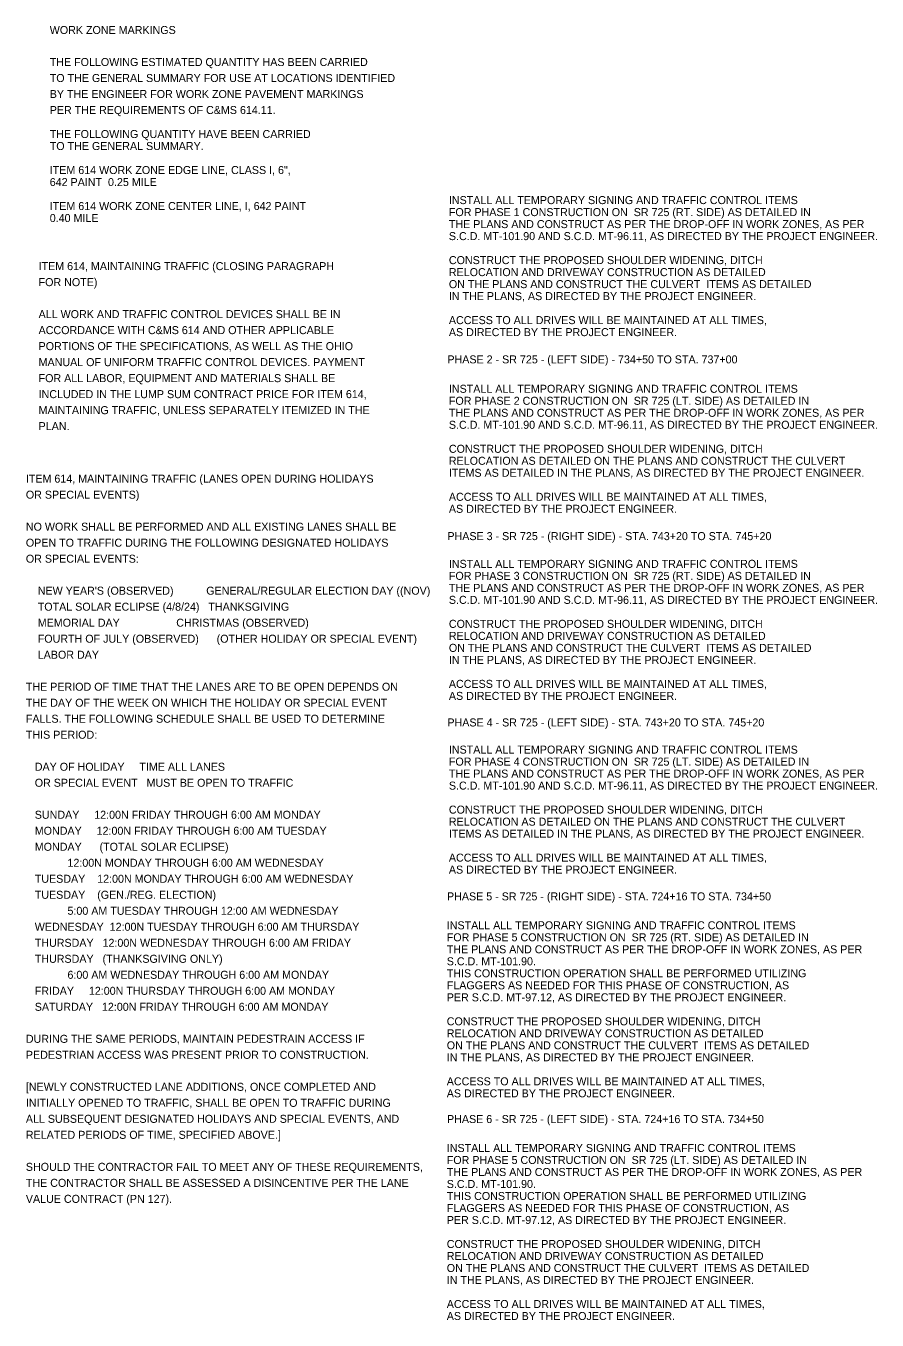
# Model space of a CAD drawing. Extents: x -18.6 to 32.6, y -1 to 22.8.
# Drawn here: x -18.64 to -3.74, y -0.08 to 22.57 of the extents above; entities that cross this region are included whole.
import ezdxf

# ---------------------------------------------------------------- set-up
doc = ezdxf.new("R2010")
doc.units = 0
doc.layers.add('SH_Text', color=7, linetype='Continuous')

msp = doc.modelspace()

# ---------------------------------------------------------------- texts
at = {"layer": 'SH_Text'}
for s, p in [('WORK ZONE MARKINGS ', (-18.224, 22.424)), ('THE FOLLOWING ESTIMATED QUANTITY HAS BEEN CARRIED', (-18.224, 21.864)), ('TO THE GENERAL SUMMARY FOR USE AT LOCATIONS IDENTIFIED', (-18.224, 21.584)), ('BY THE ENGINEER FOR WORK ZONE PAVEMENT MARKINGS', (-18.224, 21.304)), ('PER THE REQUIREMENTS OF C&MS 614.11.', (-18.224, 21.024)), ('THE FOLLOWING QUANTITY HAVE BEEN CARRIED ', (-18.224, 20.604)), ('TO THE GENERAL SUMMARY.', (-18.224, 20.394)), ('ITEM 614 WORK ZONE EDGE LINE, CLASS I, 6", ', (-18.224, 19.974)), ('642 PAINT  0.25 MILE', (-18.224, 19.764)), ('ITEM 614 WORK ZONE CENTER LINE, I, 642 PAINT', (-18.224, 19.344)), ('INSTALL ALL TEMPORARY SIGNING AND TRAFFIC CONTROL ITEMS', (-11.239, 19.448)), ('0.40 MILE', (-18.224, 19.134)), ('FOR PHASE 1 CONSTRUCTION ON  SR 725 (RT. SIDE) AS DETAILED IN', (-11.239, 19.238)), ('THE PLANS AND CONSTRUCT AS PER THE DROP-OFF IN WORK ZONES, AS PER ', (-11.239, 19.028)), ('S.C.D. MT-101.90 AND S.C.D. MT-96.11, AS DIRECTED BY THE PROJECT ENGINEER.', (-11.239, 18.818)), ('ITEM 614, MAINTAINING TRAFFIC (CLOSING PARAGRAPH', (-18.419, 18.293)), ('CONSTRUCT THE PROPOSED SHOULDER WIDENING, DITCH ', (-11.239, 18.398)), ('FOR NOTE)', (-18.419, 18.013)), ('ON THE PLANS AND CONSTRUCT THE CULVERT  ITEMS AS DETAILED ', (-11.239, 17.978)), ('RELOCATION AND DRIVEWAY CONSTRUCTION AS DETAILED ', (-11.239, 18.188)), ('IN THE PLANS, AS DIRECTED BY THE PROJECT ENGINEER.', (-11.239, 17.768)), ('ALL WORK AND TRAFFIC CONTROL DEVICES SHALL BE IN', (-18.419, 17.453)), ('ACCESS TO ALL DRIVES WILL BE MAINTAINED AT ALL TIMES, ', (-11.239, 17.348)), ('ACCORDANCE WITH C&MS 614 AND OTHER APPLICABLE', (-18.419, 17.173)), ('AS DIRECTED BY THE PROJECT ENGINEER.', (-11.239, 17.138)), ('PORTIONS OF THE SPECIFICATIONS, AS WELL AS THE OHIO', (-18.419, 16.893)), ('PHASE 2 - SR 725 - (LEFT SIDE) - 734+50 TO STA. 737+00', (-11.265, 16.661)), ('MANUAL OF UNIFORM TRAFFIC CONTROL DEVICES. PAYMENT', (-18.419, 16.613)), ('FOR ALL LABOR, EQUIPMENT AND MATERIALS SHALL BE', (-18.419, 16.333)), ('INCLUDED IN THE LUMP SUM CONTRACT PRICE FOR ITEM 614,', (-18.419, 16.053)), ('FOR PHASE 2 CONSTRUCTION ON  SR 725 (LT. SIDE) AS DETAILED IN', (-11.239, 15.937)), ('INSTALL ALL TEMPORARY SIGNING AND TRAFFIC CONTROL ITEMS', (-11.239, 16.147)), ('MAINTAINING TRAFFIC, UNLESS SEPARATELY ITEMIZED IN THE', (-18.419, 15.773)), ('THE PLANS AND CONSTRUCT AS PER THE DROP-OFF IN WORK ZONES, AS PER ', (-11.239, 15.727)), ('PLAN.', (-18.419, 15.493)), ('S.C.D. MT-101.90 AND S.C.D. MT-96.11, AS DIRECTED BY THE PROJECT ENGINEER.', (-11.239, 15.517)), ('CONSTRUCT THE PROPOSED SHOULDER WIDENING, DITCH ', (-11.239, 15.097)), ('RELOCATION AS DETAILED ON THE PLANS AND CONSTRUCT THE CULVERT  ', (-11.239, 14.887)), ('ITEM 614, MAINTAINING TRAFFIC (LANES OPEN DURING HOLIDAYS', (-18.642, 14.574)), ('ITEMS AS DETAILED IN THE PLANS, AS DIRECTED BY THE PROJECT ENGINEER.', (-11.239, 14.677)), ('OR SPECIAL EVENTS)', (-18.642, 14.294)), ('ACCESS TO ALL DRIVES WILL BE MAINTAINED AT ALL TIMES, ', (-11.239, 14.257)), ('AS DIRECTED BY THE PROJECT ENGINEER.', (-11.239, 14.047)), ('NO WORK SHALL BE PERFORMED AND ALL EXISTING LANES SHALL BE', (-18.642, 13.734)), ('OPEN TO TRAFFIC DURING THE FOLLOWING DESIGNATED HOLIDAYS', (-18.642, 13.454)), ('PHASE 3 - SR 725 - (RIGHT SIDE) - STA. 743+20 TO STA. 745+20', (-11.265, 13.569)), ('OR SPECIAL EVENTS:', (-18.642, 13.174)), ('INSTALL ALL TEMPORARY SIGNING AND TRAFFIC CONTROL ITEMS', (-11.239, 13.084)), ('FOR PHASE 3 CONSTRUCTION ON  SR 725 (RT. SIDE) AS DETAILED IN', (-11.239, 12.874)), ("    NEW YEAR'S (OBSERVED)           GENERAL/REGULAR ELECTION DAY ((NOV)", (-18.642, 12.614)), ('THE PLANS AND CONSTRUCT AS PER THE DROP-OFF IN WORK ZONES, AS PER ', (-11.239, 12.664)), ('    TOTAL SOLAR ECLIPSE (4/8/24)   THANKSGIVING', (-18.642, 12.334)), ('S.C.D. MT-101.90 AND S.C.D. MT-96.11, AS DIRECTED BY THE PROJECT ENGINEER.', (-11.239, 12.454)), ('    MEMORIAL DAY                   CHRISTMAS (OBSERVED)', (-18.642, 12.054)), ('CONSTRUCT THE PROPOSED SHOULDER WIDENING, DITCH ', (-11.239, 12.034)), ('    FOURTH OF JULY (OBSERVED)      (OTHER HOLIDAY OR SPECIAL EVENT)', (-18.642, 11.774)), ('RELOCATION AND DRIVEWAY CONSTRUCTION AS DETAILED ', (-11.239, 11.824)), ('    LABOR DAY', (-18.642, 11.494)), ('ON THE PLANS AND CONSTRUCT THE CULVERT  ITEMS AS DETAILED ', (-11.239, 11.614)), ('IN THE PLANS, AS DIRECTED BY THE PROJECT ENGINEER.', (-11.239, 11.404)), ('ACCESS TO ALL DRIVES WILL BE MAINTAINED AT ALL TIMES, ', (-11.239, 10.984)), ('THE PERIOD OF TIME THAT THE LANES ARE TO BE OPEN DEPENDS ON', (-18.642, 10.934)), ('AS DIRECTED BY THE PROJECT ENGINEER.', (-11.239, 10.774)), ('THE DAY OF THE WEEK ON WHICH THE HOLIDAY OR SPECIAL EVENT', (-18.642, 10.654)), ('FALLS. THE FOLLOWING SCHEDULE SHALL BE USED TO DETERMINE', (-18.642, 10.374)), ('PHASE 4 - SR 725 - (LEFT SIDE) - STA. 743+20 TO STA. 745+20', (-11.265, 10.309)), ('THIS PERIOD:', (-18.642, 10.094)), ('INSTALL ALL TEMPORARY SIGNING AND TRAFFIC CONTROL ITEMS', (-11.239, 9.834)), ('FOR PHASE 4 CONSTRUCTION ON  SR 725 (LT. SIDE) AS DETAILED IN', (-11.239, 9.624)), ('   DAY OF HOLIDAY     TIME ALL LANES', (-18.642, 9.534)), ('THE PLANS AND CONSTRUCT AS PER THE DROP-OFF IN WORK ZONES, AS PER ', (-11.239, 9.414)), ('   OR SPECIAL EVENT   MUST BE OPEN TO TRAFFIC', (-18.642, 9.254)), ('S.C.D. MT-101.90 AND S.C.D. MT-96.11, AS DIRECTED BY THE PROJECT ENGINEER.', (-11.239, 9.204)), ('   SUNDAY     12:00N FRIDAY THROUGH 6:00 AM MONDAY', (-18.642, 8.694)), ('CONSTRUCT THE PROPOSED SHOULDER WIDENING, DITCH ', (-11.239, 8.784)), ('RELOCATION AS DETAILED ON THE PLANS AND CONSTRUCT THE CULVERT  ', (-11.239, 8.574)), ('   MONDAY     12:00N FRIDAY THROUGH 6:00 AM TUESDAY', (-18.642, 8.414)), ('ITEMS AS DETAILED IN THE PLANS, AS DIRECTED BY THE PROJECT ENGINEER.', (-11.239, 8.364)), ('   MONDAY      (TOTAL SOLAR ECLIPSE)', (-18.642, 8.134)), ('              12:00N MONDAY THROUGH 6:00 AM WEDNESDAY', (-18.642, 7.854)), ('ACCESS TO ALL DRIVES WILL BE MAINTAINED AT ALL TIMES, ', (-11.239, 7.944)), ('   TUESDAY    12:00N MONDAY THROUGH 6:00 AM WEDNESDAY', (-18.642, 7.574)), ('AS DIRECTED BY THE PROJECT ENGINEER.', (-11.239, 7.734)), ('   TUESDAY    (GEN./REG. ELECTION)', (-18.642, 7.294)), ('PHASE 5 - SR 725 - (RIGHT SIDE) - STA. 724+16 TO STA. 734+50', (-11.272, 7.266)), ('              5:00 AM TUESDAY THROUGH 12:00 AM WEDNESDAY', (-18.642, 7.014)), ('   WEDNESDAY  12:00N TUESDAY THROUGH 6:00 AM THURSDAY', (-18.642, 6.734)), ('INSTALL ALL TEMPORARY SIGNING AND TRAFFIC CONTROL ITEMS', (-11.276, 6.76)), ('   THURSDAY   12:00N WEDNESDAY THROUGH 6:00 AM FRIDAY', (-18.642, 6.454)), ('FOR PHASE 5 CONSTRUCTION ON  SR 725 (RT. SIDE) AS DETAILED IN', (-11.276, 6.55)), ('THE PLANS AND CONSTRUCT AS PER THE DROP-OFF IN WORK ZONES, AS PER ', (-11.276, 6.34)), ('   THURSDAY   (THANKSGIVING ONLY)', (-18.642, 6.174)), ('S.C.D. MT-101.90.', (-11.276, 6.13)), ('              6:00 AM WEDNESDAY THROUGH 6:00 AM MONDAY', (-18.642, 5.894)), ('THIS CONSTRUCTION OPERATION SHALL BE PERFORMED UTILIZING', (-11.276, 5.92)), ('   FRIDAY     12:00N THURSDAY THROUGH 6:00 AM MONDAY', (-18.642, 5.614)), ('FLAGGERS AS NEEDED FOR THIS PHASE OF CONSTRUCTION, AS ', (-11.276, 5.71)), ('   SATURDAY   12:00N FRIDAY THROUGH 6:00 AM MONDAY', (-18.642, 5.334)), ('PER S.C.D. MT-97.12, AS DIRECTED BY THE PROJECT ENGINEER.', (-11.276, 5.5)), ('CONSTRUCT THE PROPOSED SHOULDER WIDENING, DITCH ', (-11.276, 5.08)), ('RELOCATION AND DRIVEWAY CONSTRUCTION AS DETAILED ', (-11.276, 4.87)), ('DURING THE SAME PERIODS, MAINTAIN PEDESTRAIN ACCESS IF', (-18.642, 4.774)), ('ON THE PLANS AND CONSTRUCT THE CULVERT  ITEMS AS DETAILED ', (-11.276, 4.66)), ('PEDESTRIAN ACCESS WAS PRESENT PRIOR TO CONSTRUCTION.', (-18.642, 4.494)), ('IN THE PLANS, AS DIRECTED BY THE PROJECT ENGINEER.', (-11.276, 4.45)), ('[NEWLY CONSTRUCTED LANE ADDITIONS, ONCE COMPLETED AND', (-18.642, 3.934)), ('ACCESS TO ALL DRIVES WILL BE MAINTAINED AT ALL TIMES, ', (-11.276, 4.03)), ('AS DIRECTED BY THE PROJECT ENGINEER.', (-11.276, 3.82)), ('INITIALLY OPENED TO TRAFFIC, SHALL BE OPEN TO TRAFFIC DURING', (-18.642, 3.654)), ('ALL SUBSEQUENT DESIGNATED HOLIDAYS AND SPECIAL EVENTS, AND', (-18.642, 3.374)), ('PHASE 6 - SR 725 - (LEFT SIDE) - STA. 724+16 TO STA. 734+50', (-11.272, 3.37)), ('RELATED PERIODS OF TIME, SPECIFIED ABOVE.]', (-18.642, 3.094)), ('INSTALL ALL TEMPORARY SIGNING AND TRAFFIC CONTROL ITEMS', (-11.276, 2.864)), ('FOR PHASE 5 CONSTRUCTION ON  SR 725 (LT. SIDE) AS DETAILED IN', (-11.276, 2.654)), ('SHOULD THE CONTRACTOR FAIL TO MEET ANY OF THESE REQUIREMENTS,', (-18.642, 2.534)), ('THE PLANS AND CONSTRUCT AS PER THE DROP-OFF IN WORK ZONES, AS PER ', (-11.276, 2.444)), ('THE CONTRACTOR SHALL BE ASSESSED A DISINCENTIVE PER THE LANE', (-18.642, 2.254)), ('S.C.D. MT-101.90.', (-11.276, 2.234)), ('VALUE CONTRACT (PN 127).', (-18.642, 1.974)), ('THIS CONSTRUCTION OPERATION SHALL BE PERFORMED UTILIZING', (-11.276, 2.024)), ('FLAGGERS AS NEEDED FOR THIS PHASE OF CONSTRUCTION, AS ', (-11.276, 1.814)), ('PER S.C.D. MT-97.12, AS DIRECTED BY THE PROJECT ENGINEER.', (-11.276, 1.604)), ('CONSTRUCT THE PROPOSED SHOULDER WIDENING, DITCH ', (-11.276, 1.184)), ('ON THE PLANS AND CONSTRUCT THE CULVERT  ITEMS AS DETAILED ', (-11.276, 0.764)), ('RELOCATION AND DRIVEWAY CONSTRUCTION AS DETAILED ', (-11.276, 0.974)), ('IN THE PLANS, AS DIRECTED BY THE PROJECT ENGINEER.', (-11.276, 0.554)), ('ACCESS TO ALL DRIVES WILL BE MAINTAINED AT ALL TIMES, ', (-11.276, 0.134)), ('AS DIRECTED BY THE PROJECT ENGINEER.', (-11.276, -0.076))]:
    msp.add_text(s, height=0.14, dxfattribs=at).set_placement(p)

doc.saveas('drawing.dxf')
